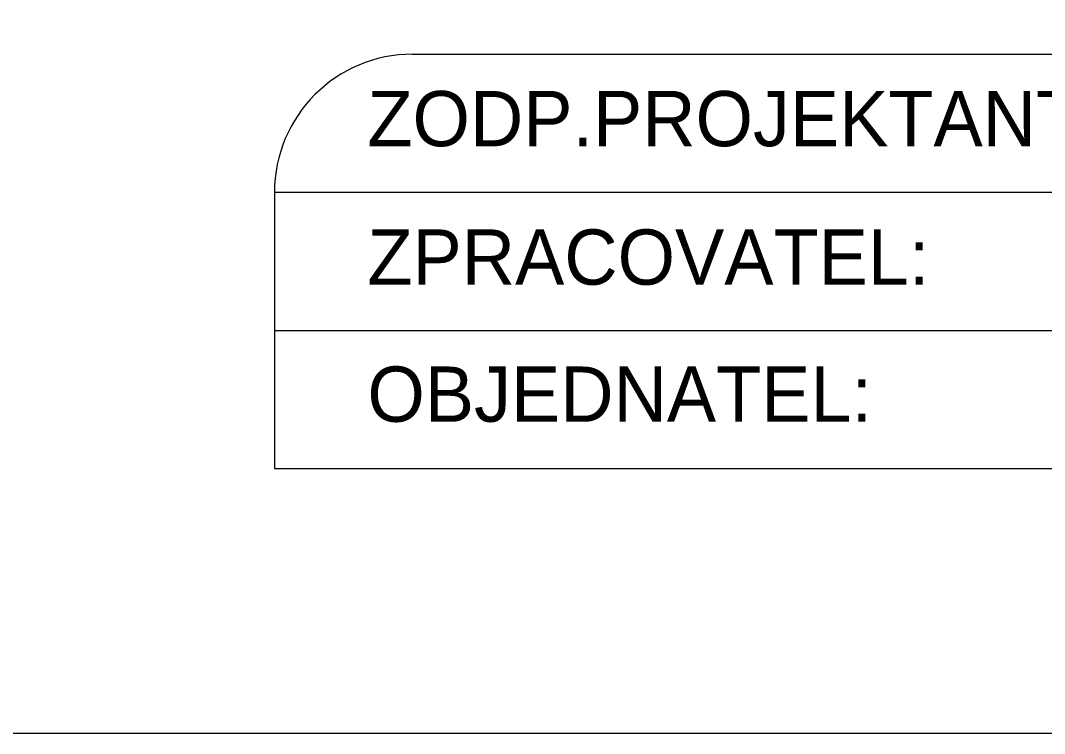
# Model space of a CAD drawing. Extents: x -443494 to -430443, y -1146902 to -1140081.
# Drawn here: x -435020.5 to -434789, y -1143080.8 to -1142919.7 of the extents above; entities that cross this region are included whole.
import ezdxf

# ---------------------------------------------------------------- set-up
doc = ezdxf.new("R2010")
doc.units = 0
doc.layers.add('Vrstva 1', color=7, linetype='Continuous')

msp = doc.modelspace()

# ---------------------------------------------------------------- linework, layer by layer
at = {"layer": 'Vrstva 1'}
for p, q in [((-434931.88, -1142927.32), (-434047.88, -1142927.32)), ((-434931.88, -1142927.32), (-434047.88, -1142927.32)), ((-434931.88, -1142927.32), (-434047.88, -1142927.32)), ((-434931.88, -1142927.32), (-434047.88, -1142927.32)), ((-434931.88, -1142927.32), (-434047.88, -1142927.32)), ((-434931.88, -1142927.32), (-434047.88, -1142927.32)), ((-434931.88, -1142927.32), (-434047.88, -1142927.32)), ((-434931.88, -1142927.32), (-434047.88, -1142927.32)), ((-434963.08, -1142958.52), (-434047.88, -1142958.52)), ((-434963.08, -1142958.52), (-434963.08, -1143020.92)), ((-434963.08, -1142958.52), (-434047.88, -1142958.52)), ((-434963.08, -1142958.52), (-434963.08, -1143020.92)), ((-434963.08, -1142958.52), (-434047.88, -1142958.52)), ((-434963.08, -1142958.52), (-434963.08, -1143020.92)), ((-434963.08, -1142958.52), (-434047.88, -1142958.52)), ((-434963.08, -1142958.52), (-434963.08, -1143020.92)), ((-434963.08, -1142958.52), (-434047.88, -1142958.52)), ((-434963.08, -1142958.52), (-434963.08, -1143020.92)), ((-434963.08, -1142958.52), (-434047.88, -1142958.52)), ((-434963.08, -1142958.52), (-434963.08, -1143020.92)), ((-434963.08, -1142958.52), (-434047.88, -1142958.52)), ((-434963.08, -1142958.52), (-434963.08, -1143020.92)), ((-434963.08, -1142958.52), (-434047.88, -1142958.52)), ((-434963.08, -1142958.52), (-434963.08, -1143020.92)), ((-434963.08, -1142989.72), (-434047.88, -1142989.72)), ((-434963.08, -1142989.72), (-434047.88, -1142989.72)), ((-434963.08, -1142989.72), (-434047.88, -1142989.72)), ((-434963.08, -1142989.72), (-434047.88, -1142989.72)), ((-434963.08, -1142989.72), (-434047.88, -1142989.72)), ((-434963.08, -1142989.72), (-434047.88, -1142989.72)), ((-434963.08, -1142989.72), (-434047.88, -1142989.72)), ((-434963.08, -1142989.72), (-434047.88, -1142989.72)), ((-434963.08, -1143020.92), (-434047.88, -1143020.92)), ((-434963.08, -1143020.92), (-434047.88, -1143020.92)), ((-434963.08, -1143020.92), (-434047.88, -1143020.92)), ((-434963.08, -1143020.92), (-434047.88, -1143020.92)), ((-434963.08, -1143020.92), (-434047.88, -1143020.92)), ((-434963.08, -1143020.92), (-434047.88, -1143020.92)), ((-434963.08, -1143020.92), (-434047.88, -1143020.92)), ((-434963.08, -1143020.92), (-434047.88, -1143020.92))]:
    msp.add_line(p, q, dxfattribs=at)
msp.add_lwpolyline([(-433990.008, -1140080.76), (-433990.008, -1143080.76), (-436490.008, -1143080.76), (-436490.008, -1140080.76)], close=True, dxfattribs=at)
msp.add_arc((-434931.88, -1142958.517), 31.2, 90, 180, dxfattribs=at)
msp.add_arc((-434931.88, -1142958.517), 31.2, 90, 180, dxfattribs=at)
msp.add_arc((-434931.88, -1142958.517), 31.2, 90, 180, dxfattribs=at)
msp.add_arc((-434931.88, -1142958.517), 31.2, 90, 180, dxfattribs=at)
msp.add_arc((-434931.88, -1142958.517), 31.2, 90, 180, dxfattribs=at)
msp.add_arc((-434931.88, -1142958.517), 31.2, 90, 180, dxfattribs=at)
msp.add_arc((-434931.88, -1142958.517), 31.2, 90, 180, dxfattribs=at)
msp.add_arc((-434931.88, -1142958.517), 31.2, 90, 180, dxfattribs=at)

# ---------------------------------------------------------------- texts
for s, p in [('ZODP.PROJEKTANT:', (-434942.067, -1142948.11)), ('ZODP.PROJEKTANT:', (-434942.067, -1142948.11)), ('ZODP.PROJEKTANT:', (-434942.067, -1142948.11)), ('ZODP.PROJEKTANT:', (-434942.067, -1142948.11)), ('ZODP.PROJEKTANT:', (-434942.067, -1142948.11)), ('ZODP.PROJEKTANT:', (-434942.067, -1142948.11)), ('ZODP.PROJEKTANT:', (-434942.067, -1142948.11)), ('ZODP.PROJEKTANT:', (-434942.067, -1142948.11)), ('ZPRACOVATEL:', (-434942.067, -1142979.388)), ('ZPRACOVATEL:', (-434942.067, -1142979.388)), ('ZPRACOVATEL:', (-434942.067, -1142979.388)), ('ZPRACOVATEL:', (-434942.067, -1142979.388)), ('ZPRACOVATEL:', (-434942.067, -1142979.388)), ('ZPRACOVATEL:', (-434942.067, -1142979.388)), ('ZPRACOVATEL:', (-434942.067, -1142979.388)), ('ZPRACOVATEL:', (-434942.067, -1142979.388)), ('OBJEDNATEL:', (-434942.067, -1143010.343)), ('OBJEDNATEL:', (-434942.067, -1143010.343)), ('OBJEDNATEL:', (-434942.067, -1143010.343)), ('OBJEDNATEL:', (-434942.067, -1143010.343)), ('OBJEDNATEL:', (-434942.067, -1143010.343)), ('OBJEDNATEL:', (-434942.067, -1143010.343)), ('OBJEDNATEL:', (-434942.067, -1143010.343)), ('OBJEDNATEL:', (-434942.067, -1143010.343))]:
    msp.add_text(s, height=12.48, dxfattribs=at).set_placement(p)

doc.saveas('drawing.dxf')
